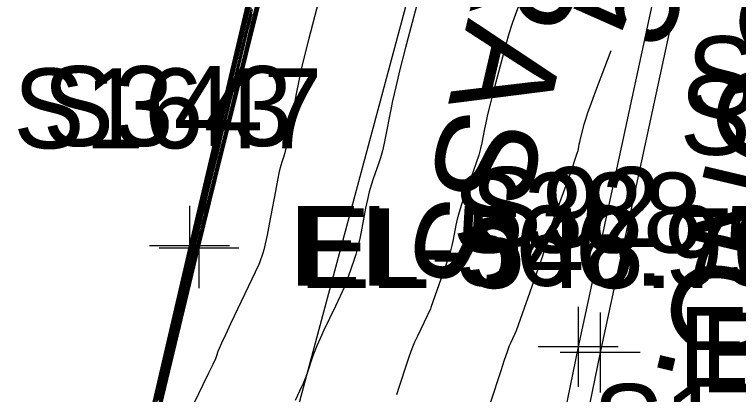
# Model space of a CAD drawing. Extents: x 1724534 to 1727318, y 657156 to 660047.
# Drawn here: x 1725584.68 to 1725620.89, y 659683.28 to 659702.31 of the extents above; entities that cross this region are included whole.
import ezdxf

# ---------------------------------------------------------------- set-up
doc = ezdxf.new("R2010")
doc.units = 0
for name, color, linetype in [('SURVEY - CONTOURS - Index with Text', 7, 'Continuous'), ('SURVEY - CONTOURS - Intermediate with optional Text', 7, 'Continuous'), ('SURVEY - DTM - Breaklines', 7, 'Continuous'), ('SURVEY - DTM - Breaklines - Points - Elevations', 7, 'Continuous'), ('SURVEY - DTM - Breaklines - Points - Locators', 7, 'Continuous'), ('SURVEY - DTM - Breaklines - Points - Numbers', 7, 'Continuous'), ('SURVEY - NON-TRANSPORTATION - Features', 7, 'Continuous'), ('SURVEY - NON-TRANSPORTATION - Features - Points - Elevations', 7, 'Continuous'), ('SURVEY - NON-TRANSPORTATION - Features - Points - Locators', 7, 'Continuous'), ('SURVEY - NON-TRANSPORTATION - Features - Points - Numbers', 7, 'Continuous'), ('SURVEY - TRANSPORTATION - Features', 7, 'Continuous'), ('SURVEY - TRANSPORTATION - Features - Points - Elevations', 7, 'Continuous'), ('SURVEY - TRANSPORTATION - Features - Points - Locators', 7, 'Continuous'), ('SURVEY - TRANSPORTATION - Features - Points - Numbers', 7, 'Continuous'), ('SURVEY - TRANSPORTATION - Features Text', 7, 'Continuous'), ('SURVEY - TRANSPORTATION - Roads - Points - Numbers', 7, 'Continuous'), ('SURVEY - UTILITIES - Fiber Optic Cable (Underground) with Text', 7, 'Continuous'), ('SURVEY - VEGETATION - Features with Text', 7, 'Continuous')]:
    doc.layers.add(name, color=color, linetype=linetype)

msp = doc.modelspace()

# ---------------------------------------------------------------- linework, layer by layer
at = {"layer": 'SURVEY - CONTOURS - Index with Text'}
for points in [[(1725591.606, 659682.65), (1725592.009, 659684.387), (1725592.143, 659684.966), (1725592.245, 659685.403), (1725592.313, 659685.697), (1725592.349, 659685.847), (1725592.399, 659686.058), (1725592.435, 659686.208), (1725592.503, 659686.502), (1725592.605, 659686.939), (1725592.739, 659687.519), (1725593.142, 659689.256), (1725593.274, 659689.826), (1725593.368, 659690.234), (1725593.426, 659690.48), (1725593.445, 659690.564), (1725593.447, 659690.571), (1725593.448, 659690.576), (1725593.45, 659690.586), (1725593.453, 659690.599), (1725593.457, 659690.617), (1725593.47, 659690.671), (1725593.493, 659690.769), (1725593.553, 659691.023), (1725593.65, 659691.433), (1725593.784, 659691.998), (1725594.191, 659693.714), (1725594.328, 659694.287), (1725594.431, 659694.721), (1725594.501, 659695.016), (1725594.539, 659695.171), (1725594.596, 659695.4), (1725594.634, 659695.554), (1725594.704, 659695.846), (1725594.806, 659696.276), (1725594.941, 659696.843), (1725595.343, 659698.539), (1725595.478, 659699.107), (1725595.581, 659699.539), (1725595.652, 659699.836), (1725595.691, 659699.997), (1725595.753, 659700.244), (1725595.792, 659700.404), (1725595.862, 659700.698), (1725595.964, 659701.126), (1725596.098, 659701.688), (1725596.496, 659703.365)], [(1725614.505, 659700.498), (1725613.696, 659698.346), (1725613.501, 659697.82), (1725613.346, 659697.387), (1725613.233, 659697.046), (1725613.16, 659696.799), (1725612.973, 659696.077), (1725612.935, 659695.922), (1725612.906, 659695.797), (1725612.887, 659695.702), (1725612.847, 659695.49), (1725612.806, 659695.342), (1725612.711, 659695.055), (1725612.564, 659694.631), (1725612.364, 659694.069), (1725611.76, 659692.386), (1725611.559, 659691.821), (1725611.411, 659691.389), (1725611.314, 659691.09), (1725611.269, 659690.923), (1725611.218, 659690.655), (1725611.175, 659690.492), (1725611.084, 659690.206), (1725610.945, 659689.795), (1725610.758, 659689.261), (1725609.771, 659686.469), (1725609.498, 659685.893), (1725609.424, 659685.715), (1725609.317, 659685.419), (1725609.175, 659685.005), (1725608.999, 659684.474), (1725608.484, 659682.9)], [(1725595.875, 659698.678), (1725595.138, 659695.716), (1725595.001, 659695.157), (1725593.931, 659690.856), (1725593.677, 659689.786), (1725592.642, 659685.467), (1725592.503, 659684.88), (1725591.476, 659680.593), (1725591.33, 659679.975), (1725590.347, 659675.869), (1725590.312, 659675.719), (1725590.159, 659675.071), (1725588.166, 659666.752), (1725588.013, 659666.093), (1725586.735, 659660.334), (1725586.015, 659657.096)], [(1725591.839, 659683.103), (1725591.939, 659683.535), (1725592.22, 659684.747), (1725592.32, 659685.179), (1725592.411, 659685.567), (1725592.492, 659685.912), (1725592.564, 659686.212), (1725592.742, 659686.954), (1725592.813, 659687.254), (1725592.894, 659687.597), (1725592.985, 659687.983), (1725593.085, 659688.413), (1725593.364, 659689.618), (1725593.456, 659690.014), (1725593.522, 659690.3), (1725593.563, 659690.476), (1725593.578, 659690.541), (1725593.584, 659690.567), (1725593.587, 659690.577), (1725593.59, 659690.589), (1725593.593, 659690.601), (1725593.596, 659690.615), (1725593.604, 659690.652), (1725593.62, 659690.72), (1725593.662, 659690.896), (1725593.729, 659691.18), (1725593.822, 659691.572), (1725593.865, 659691.751)], [(1725593.278, 659688.662), (1725593.085, 659687.85), (1725592.578, 659685.732), (1725592.126, 659683.798), (1725591.424, 659680.865), (1725590.966, 659678.905), (1725590.271, 659675.998), (1725589.807, 659674.012), (1725588.399, 659668.125), (1725588.074, 659666.734), (1725587.908, 659666.01), (1725585.853, 659656.743)]]:
    msp.add_lwpolyline(points, dxfattribs=at)
at = {"layer": 'SURVEY - CONTOURS - Intermediate with optional Text'}
for points in [[(1725599.522, 659713.198), (1725594.751, 659694.03), (1725593.893, 659690.58), (1725591.498, 659680.584), (1725590.349, 659675.79), (1725589.977, 659674.229), (1725588.105, 659666.413), (1725587.991, 659665.913), (1725587.691, 659664.563), (1725586.902, 659661.012), (1725585.92, 659656.591)], [(1725611.985, 659708.312), (1725609.681, 659702.188), (1725609.547, 659701.805), (1725609.402, 659701.343), (1725609.246, 659700.802), (1725609.08, 659700.182), (1725608.623, 659698.424), (1725608.467, 659697.814), (1725608.341, 659697.304), (1725608.246, 659696.894), (1725608.182, 659696.583), (1725608.052, 659695.888), (1725607.989, 659695.603), (1725607.897, 659695.268), (1725607.776, 659694.884), (1725607.626, 659694.451), (1725607.188, 659693.23), (1725607.038, 659692.796), (1725606.916, 659692.407), (1725606.822, 659692.065), (1725606.756, 659691.769), (1725606.618, 659691.042), (1725606.553, 659690.748), (1725606.463, 659690.415), (1725606.348, 659690.04), (1725606.207, 659689.625), (1725605.503, 659687.637), (1725605.48, 659687.574), (1725604.829, 659686.201), (1725604.693, 659685.9), (1725604.557, 659685.565), (1725604.421, 659685.196), (1725604.284, 659684.793), (1725603.919, 659683.675), (1725603.78, 659683.269)], [(1725597.458, 659705.207), (1725596.393, 659700.922), (1725596.256, 659700.353), (1725595.19, 659696.064), (1725595.054, 659695.499), (1725593.987, 659691.206), (1725593.764, 659690.269), (1725593.599, 659689.567), (1725592.639, 659685.562), (1725592.428, 659684.664), (1725591.477, 659680.694), (1725591.258, 659679.761), (1725590.316, 659675.826), (1725590.089, 659674.859), (1725588.197, 659666.958), (1725588.152, 659666.769), (1725587.998, 659666.1), (1725585.808, 659656.238)], [(1725593.678, 659691.782), (1725595.817, 659700.79), (1725596.879, 659705.257)], [(1725597.105, 659704.079), (1725596.504, 659701.666), (1725596.375, 659701.133), (1725596.215, 659700.463), (1725595.909, 659699.226), (1725595.309, 659696.814), (1725595.179, 659696.28), (1725595.019, 659695.61), (1725594.713, 659694.373), (1725594.113, 659691.961), (1725593.983, 659691.428), (1725593.711, 659690.277), (1725593.517, 659689.446), (1725592.568, 659685.477), (1725592.277, 659684.231), (1725591.41, 659680.609), (1725591.112, 659679.333), (1725590.253, 659675.741), (1725589.948, 659674.436), (1725588.334, 659667.694), (1725588.073, 659666.578), (1725587.937, 659665.983), (1725584.959, 659652.565)], [(1725597.088, 659704.163), (1725596.523, 659701.891), (1725596.385, 659701.319), (1725596.194, 659700.519), (1725595.896, 659699.311), (1725595.331, 659697.041), (1725595.192, 659696.469), (1725595.001, 659695.666), (1725594.703, 659694.458), (1725594.139, 659692.191), (1725594, 659691.618), (1725593.674, 659690.24), (1725593.441, 659689.237), (1725593.153, 659688.029), (1725592.611, 659685.765), (1725592.473, 659685.179), (1725592.279, 659684.342), (1725591.992, 659683.139)], [(1725597.121, 659703.995), (1725596.485, 659701.442), (1725596.364, 659700.947), (1725596.236, 659700.408), (1725595.921, 659699.141), (1725595.286, 659696.587), (1725595.165, 659696.092), (1725595.037, 659695.555), (1725594.722, 659694.287), (1725594.086, 659691.731), (1725593.965, 659691.237), (1725593.72, 659690.197), (1725593.521, 659689.348), (1725592.604, 659685.52), (1725592.352, 659684.447), (1725591.444, 659680.652), (1725591.185, 659679.547), (1725590.284, 659675.783), (1725590.018, 659674.647), (1725588.302, 659667.479), (1725588.072, 659666.499), (1725587.949, 659665.958), (1725585.852, 659656.511)], [(1725591.54, 659682.473), (1725591.967, 659684.314), (1725592.108, 659684.924), (1725592.211, 659685.37), (1725592.277, 659685.654), (1725592.306, 659685.774), (1725592.331, 659685.879), (1725592.359, 659685.999), (1725592.425, 659686.283), (1725592.529, 659686.73), (1725592.67, 659687.34), (1725593.097, 659689.183), (1725593.237, 659689.788), (1725593.338, 659690.221), (1725593.398, 659690.481), (1725593.418, 659690.568), (1725593.419, 659690.572), (1725593.42, 659690.576), (1725593.422, 659690.585), (1725593.425, 659690.599), (1725593.43, 659690.618), (1725593.443, 659690.675), (1725593.468, 659690.779), (1725593.532, 659691.049), (1725593.635, 659691.483), (1725593.777, 659692.084), (1725594.209, 659693.904), (1725594.352, 659694.507), (1725594.457, 659694.951), (1725594.525, 659695.236), (1725594.556, 659695.362), (1725594.586, 659695.485), (1725594.616, 659695.61), (1725594.684, 659695.892), (1725594.788, 659696.331), (1725594.93, 659696.927), (1725595.357, 659698.727), (1725595.499, 659699.324), (1725595.604, 659699.766), (1725595.672, 659700.053), (1725595.704, 659700.185), (1725595.74, 659700.329), (1725595.772, 659700.46), (1725595.839, 659700.744), (1725595.944, 659701.181), (1725596.084, 659701.772), (1725596.506, 659703.551)], [(1725591.672, 659682.499), (1725592.378, 659685.535), (1725592.521, 659686.139), (1725592.738, 659687.044), (1725593.016, 659688.234), (1725593.595, 659690.73), (1725594.122, 659692.952), (1725594.23, 659693.407), (1725594.406, 659694.135), (1725594.702, 659695.33), (1725594.984, 659696.505), (1725595.49, 659698.631), (1725595.64, 659699.243), (1725595.873, 659700.181), (1725596.154, 659701.352), (1725596.657, 659703.461)], [(1725605, 659703.565), (1725604.225, 659700.584), (1725603.96, 659699.551), (1725603.747, 659698.686), (1725603.587, 659697.991), (1725603.478, 659697.465), (1725603.257, 659696.286), (1725603.172, 659695.864), (1725603.082, 659695.481), (1725602.988, 659695.137), (1725602.888, 659694.833), (1725602.616, 659694.075), (1725602.516, 659693.771), (1725602.42, 659693.426), (1725602.329, 659693.041), (1725602.243, 659692.616), (1725602.018, 659691.428), (1725601.932, 659691.004), (1725601.843, 659690.623), (1725601.75, 659690.285), (1725601.655, 659689.989), (1725601.248, 659688.839), (1725601.189, 659688.679), (1725600.728, 659687.709), (1725600.159, 659686.51), (1725599.962, 659686.085), (1725599.798, 659685.711), (1725599.668, 659685.387), (1725599.57, 659685.113), (1725599.353, 659684.45), (1725599.253, 659684.172), (1725599.115, 659683.836), (1725598.938, 659683.441), (1725598.724, 659682.988)], [(1725591.673, 659682.827), (1725592.051, 659684.459), (1725592.179, 659685.009), (1725592.278, 659685.436), (1725592.349, 659685.74), (1725592.468, 659686.237), (1725592.51, 659686.417), (1725592.581, 659686.721), (1725592.681, 659687.148), (1725592.808, 659687.698), (1725593.31, 659689.864), (1725593.399, 659690.247), (1725593.453, 659690.479), (1725593.472, 659690.559), (1725593.474, 659690.57), (1725593.478, 659690.586), (1725593.481, 659690.6), (1725593.485, 659690.617), (1725593.497, 659690.667), (1725593.519, 659690.76), (1725593.666, 659691.382), (1725593.792, 659691.913), (1725594.174, 659693.523), (1725594.303, 659694.067), (1725594.404, 659694.491), (1725594.523, 659694.981), (1725594.606, 659695.314), (1725594.651, 659695.498), (1725594.723, 659695.8), (1725594.824, 659696.22), (1725594.952, 659696.758), (1725595.329, 659698.351), (1725595.458, 659698.89), (1725595.558, 659699.312), (1725595.632, 659699.618), (1725595.678, 659699.808), (1725595.812, 659700.348), (1725595.885, 659700.652), (1725595.985, 659701.071), (1725596.112, 659701.604), (1725596.486, 659703.179)], [(1725591.739, 659683.004), (1725592.093, 659684.531), (1725592.214, 659685.051), (1725592.311, 659685.469), (1725592.385, 659685.783), (1725592.435, 659685.993), (1725592.536, 659686.416), (1725592.586, 659686.626), (1725592.66, 659686.94), (1725592.757, 659687.357), (1725592.877, 659687.876), (1725593.231, 659689.4), (1725593.347, 659689.901), (1725593.43, 659690.26), (1725593.48, 659690.478), (1725593.498, 659690.555), (1725593.502, 659690.57), (1725593.504, 659690.577), (1725593.506, 659690.587), (1725593.509, 659690.6), (1725593.513, 659690.616), (1725593.524, 659690.664), (1725593.544, 659690.75), (1725593.597, 659690.972), (1725593.682, 659691.332), (1725593.8, 659691.828), (1725594.157, 659693.333), (1725594.279, 659693.847), (1725594.378, 659694.261), (1725594.454, 659694.576), (1725594.506, 659694.79), (1725594.615, 659695.229), (1725594.668, 659695.442), (1725594.743, 659695.754), (1725594.841, 659696.165), (1725594.962, 659696.674), (1725595.316, 659698.162), (1725595.437, 659698.672), (1725595.536, 659699.085), (1725595.612, 659699.401), (1725595.666, 659699.62), (1725595.779, 659700.074), (1725595.832, 659700.293), (1725595.908, 659700.606), (1725596.006, 659701.015), (1725596.126, 659701.52), (1725596.476, 659702.993)], [(1725599.883, 659702.961), (1725599.382, 659701.036), (1725599.203, 659700.327), (1725599.042, 659699.642), (1725598.899, 659698.981), (1725598.773, 659698.346), (1725598.463, 659696.684), (1725598.356, 659696.124), (1725598.268, 659695.693), (1725598.199, 659695.39), (1725598.15, 659695.215), (1725598.044, 659694.92), (1725597.994, 659694.745), (1725597.925, 659694.444), (1725597.837, 659694.017), (1725597.73, 659693.462), (1725597.417, 659691.815), (1725597.31, 659691.26), (1725597.222, 659690.832), (1725597.153, 659690.53), (1725597.103, 659690.353), (1725596.932, 659689.872), (1725596.897, 659689.784), (1725595.49, 659686.818), (1725595.231, 659686.27), (1725595.039, 659685.857), (1725594.914, 659685.578), (1725594.855, 659685.433), (1725594.787, 659685.225), (1725594.726, 659685.076), (1725594.592, 659684.783), (1725594.385, 659684.346), (1725594.106, 659683.766), (1725592.989, 659681.452)], [(1725591.806, 659683.181), (1725592.135, 659684.603), (1725592.25, 659685.094), (1725592.345, 659685.502), (1725592.421, 659685.826), (1725592.478, 659686.066), (1725592.605, 659686.595), (1725592.662, 659686.835), (1725592.738, 659687.159), (1725592.833, 659687.565), (1725592.947, 659688.055), (1725593.275, 659689.473), (1725593.383, 659689.939), (1725593.461, 659690.274), (1725593.508, 659690.477), (1725593.525, 659690.55), (1725593.529, 659690.569), (1725593.531, 659690.577), (1725593.534, 659690.587), (1725593.537, 659690.6), (1725593.54, 659690.616), (1725593.551, 659690.66), (1725593.57, 659690.74), (1725593.619, 659690.947), (1725593.698, 659691.281), (1725593.807, 659691.743), (1725594.139, 659693.142), (1725594.254, 659693.627), (1725594.351, 659694.031), (1725594.43, 659694.356), (1725594.49, 659694.6), (1725594.625, 659695.143), (1725594.685, 659695.386), (1725594.763, 659695.708), (1725594.859, 659696.109), (1725594.973, 659696.589), (1725595.302, 659697.974), (1725595.416, 659698.455), (1725595.513, 659698.858), (1725595.592, 659699.183), (1725595.653, 659699.432), (1725595.792, 659699.99), (1725595.853, 659700.237), (1725595.931, 659700.56), (1725596.027, 659700.96), (1725596.14, 659701.436), (1725596.466, 659702.807)], [(1725591.823, 659682.932), (1725591.912, 659683.309), (1725592.006, 659683.712), (1725592.262, 659684.819), (1725592.356, 659685.222), (1725592.445, 659685.6), (1725592.528, 659685.955), (1725592.607, 659686.285), (1725592.811, 659687.133), (1725592.889, 659687.463), (1725592.973, 659687.816), (1725593.061, 659688.192), (1725593.154, 659688.592), (1725593.408, 659689.69), (1725593.492, 659690.052), (1725593.553, 659690.313), (1725593.59, 659690.475), (1725593.605, 659690.536), (1725593.612, 659690.566), (1725593.615, 659690.578), (1725593.618, 659690.589), (1725593.62, 659690.602), (1725593.623, 659690.614), (1725593.631, 659690.648), (1725593.646, 659690.71), (1725593.684, 659690.871), (1725593.745, 659691.13), (1725593.83, 659691.487), (1725594.087, 659692.571), (1725594.181, 659692.967), (1725594.272, 659693.341), (1725594.358, 659693.695), (1725594.44, 659694.028), (1725594.654, 659694.886), (1725594.736, 659695.218), (1725594.822, 659695.571), (1725594.912, 659695.943), (1725595.006, 659696.336), (1725595.261, 659697.41), (1725595.355, 659697.803), (1725595.445, 659698.177), (1725595.531, 659698.531), (1725595.614, 659698.866), (1725595.831, 659699.735), (1725595.914, 659700.07), (1725596, 659700.423), (1725596.09, 659700.795), (1725596.183, 659701.185), (1725596.435, 659702.249), (1725596.529, 659702.639)], [(1725591.886, 659682.993), (1725591.975, 659683.365), (1725592.059, 659683.722), (1725592.139, 659684.066), (1725592.347, 659684.963), (1725592.427, 659685.307), (1725592.511, 659685.666), (1725592.948, 659687.491), (1725593.041, 659687.881), (1725593.129, 659688.254), (1725593.213, 659688.61), (1725593.292, 659688.95), (1725593.497, 659689.835), (1725593.565, 659690.127), (1725593.614, 659690.34), (1725593.645, 659690.473), (1725593.658, 659690.527), (1725593.667, 659690.564), (1725593.67, 659690.578), (1725593.673, 659690.591), (1725593.676, 659690.602), (1725593.697, 659690.691), (1725593.727, 659690.82), (1725593.777, 659691.028), (1725593.845, 659691.316), (1725594.052, 659692.19), (1725594.133, 659692.526), (1725594.219, 659692.881), (1725594.31, 659693.255), (1725594.407, 659693.646), (1725594.674, 659694.715), (1725594.771, 659695.106), (1725594.862, 659695.479), (1725594.948, 659695.832), (1725595.028, 659696.167), (1725595.314, 659697.368), (1725595.399, 659697.722), (1725595.491, 659698.096), (1725595.857, 659699.565), (1725595.954, 659699.958), (1725596.046, 659700.331), (1725596.131, 659700.684), (1725596.211, 659701.017), (1725596.415, 659701.877), (1725596.495, 659702.21), (1725596.581, 659702.564)], [(1725591.899, 659683.148), (1725591.985, 659683.516), (1725592.072, 659683.889), (1725592.304, 659684.891), (1725592.391, 659685.264), (1725592.478, 659685.633), (1725592.564, 659685.998), (1725592.65, 659686.358), (1725592.879, 659687.312), (1725592.965, 659687.672), (1725593.051, 659688.035), (1725593.137, 659688.401), (1725593.223, 659688.771), (1725593.453, 659689.762), (1725593.529, 659690.089), (1725593.584, 659690.326), (1725593.618, 659690.474), (1725593.631, 659690.531), (1725593.64, 659690.565), (1725593.643, 659690.578), (1725593.645, 659690.59), (1725593.648, 659690.602), (1725593.651, 659690.614), (1725593.658, 659690.644), (1725593.671, 659690.7), (1725593.706, 659690.845), (1725593.761, 659691.079), (1725593.838, 659691.402), (1725594.07, 659692.38), (1725594.157, 659692.747), (1725594.245, 659693.111), (1725594.334, 659693.475), (1725594.424, 659693.837), (1725594.664, 659694.801), (1725594.754, 659695.162), (1725594.842, 659695.525), (1725594.93, 659695.888), (1725595.017, 659696.251), (1725595.247, 659697.221), (1725595.334, 659697.585), (1725595.422, 659697.949), (1725595.511, 659698.314), (1725595.602, 659698.678), (1725595.844, 659699.65), (1725595.934, 659700.014), (1725596.023, 659700.377), (1725596.11, 659700.739), (1725596.197, 659701.101), (1725596.425, 659702.063), (1725596.512, 659702.425)], [(1725591.959, 659683.2), (1725592.05, 659683.581), (1725592.132, 659683.929), (1725592.205, 659684.243), (1725592.389, 659685.035), (1725592.462, 659685.349), (1725592.544, 659685.699), (1725593.016, 659687.67), (1725593.117, 659688.09), (1725593.208, 659688.472), (1725593.289, 659688.819), (1725593.361, 659689.129), (1725593.542, 659689.907), (1725593.602, 659690.165), (1725593.645, 659690.353), (1725593.673, 659690.472), (1725593.685, 659690.522), (1725593.695, 659690.563), (1725593.698, 659690.578), (1725593.701, 659690.591), (1725593.704, 659690.603), (1725593.722, 659690.681), (1725593.749, 659690.794), (1725593.853, 659691.231), (1725594.035, 659691.999), (1725594.108, 659692.306), (1725594.192, 659692.651), (1725594.286, 659693.035), (1725594.391, 659693.456), (1725594.683, 659694.629), (1725594.788, 659695.05), (1725594.882, 659695.433), (1725594.966, 659695.777), (1725595.039, 659696.082), (1725595.293, 659697.151), (1725595.377, 659697.495), (1725595.471, 659697.879), (1725595.576, 659698.301), (1725595.87, 659699.48), (1725595.974, 659699.903), (1725596.069, 659700.286), (1725596.152, 659700.629), (1725596.225, 659700.933), (1725596.405, 659701.691), (1725596.478, 659701.995), (1725596.562, 659702.339)]]:
    msp.add_lwpolyline(points, dxfattribs=at)
at = {"layer": 'SURVEY - DTM - Breaklines'}
for points in [[(1725548.52, 659521.481), (1725556.845, 659545.065), (1725562.116, 659569.482), (1725564.828, 659594.513), (1725575.937, 659617.765), (1725582.317, 659641.569), (1725587.744, 659666.22), (1725593.428, 659690.724), (1725599.084, 659714.698), (1725604.574, 659739.361), (1725605.919, 659744.429), (1725611.764, 659762.844), (1725613.112, 659786.858), (1725615.798, 659788.854), (1725620.104, 659809.038)], [(1725639.982, 659805.546), (1725635.79, 659784.47), (1725629.921, 659758.494), (1725625.443, 659739.387), (1725624.054, 659734.362), (1725618.103, 659709.974), (1725612.874, 659685.67), (1725607.844, 659661.097), (1725602.477, 659636.589), (1725597.046, 659612.281)]]:
    msp.add_lwpolyline(points, dxfattribs=at)
at = {"layer": 'SURVEY - DTM - Breaklines - Points - Locators'}
for p, q in [((1725593.428, 659692.724), (1725593.428, 659688.724)), ((1725595.428, 659690.724), (1725591.428, 659690.724)), ((1725612.874, 659687.67), (1725612.874, 659683.67)), ((1725614.874, 659685.67), (1725610.874, 659685.67))]:
    msp.add_line(p, q, dxfattribs=at)
at = {"layer": 'SURVEY - NON-TRANSPORTATION - Features'}
msp.add_lwpolyline([(1725569.664, 659593.303), (1725577.056, 659617.422), (1725582.603, 659641.503), (1725588.069, 659666.147), (1725593.908, 659690.609), (1725599.872, 659714.501), (1725606.018, 659738.998), (1725607.394, 659744.026), (1725612.585, 659762.615), (1725617.711, 659786.227), (1725616.679, 659788.487), (1725620.281, 659809.007)], dxfattribs=at)
at = {"layer": 'SURVEY - NON-TRANSPORTATION - Features - Points - Locators'}
for p, q in [((1725593.908, 659692.609), (1725593.908, 659688.609)), ((1725595.908, 659690.609), (1725591.908, 659690.609))]:
    msp.add_line(p, q, dxfattribs=at)
at = {"layer": 'SURVEY - TRANSPORTATION - Features'}
msp.add_lwpolyline([(1725641.101, 659805.349), (1725636.902, 659784.236), (1725631.028, 659758.231), (1725626.544, 659739.104), (1725625.155, 659734.079), (1725619.206, 659709.701), (1725613.974, 659685.384), (1725608.945, 659660.816), (1725603.581, 659636.317), (1725598.147, 659611.998)], dxfattribs=at)
at = {"layer": 'SURVEY - TRANSPORTATION - Features - Points - Locators'}
for p, q in [((1725613.974, 659687.384), (1725613.974, 659683.384)), ((1725615.974, 659685.384), (1725611.974, 659685.384))]:
    msp.add_line(p, q, dxfattribs=at)
at = {"layer": 'SURVEY - UTILITIES - Fiber Optic Cable (Underground) with Text'}
msp.add_lwpolyline([(1725620.739, 659775.717), (1725611.515, 659729.876), (1725595.678, 659670.817), (1725588.852, 659637.987), (1725579.945, 659608.985), (1725572.052, 659574.699), (1725561.954, 659530.586), (1725538.949, 659448.715), (1725526.808, 659392.271), (1725505.744, 659313.434), (1725493.556, 659248.407)], dxfattribs=at)

# ---------------------------------------------------------------- texts
at = {"layer": 'SURVEY - CONTOURS - Index with Text'}
msp.add_text('545', height=5, rotation=69.3885, dxfattribs=at).set_placement((1725617.117, 659700.339))
at = {"layer": 'SURVEY - DTM - Breaklines - Points - Elevations'}
for s, p in [('EL-566.95', (1725598.428, 659688.724)), ('EL-544.28', (1725617.874, 659683.67))]:
    msp.add_text(s, height=4, dxfattribs=at).set_placement(p)
at = {"layer": 'SURVEY - DTM - Breaklines - Points - Numbers'}
for s, p in [('S343', (1725586.092, 659695.724)), ('S92', (1725607.49, 659690.67))]:
    msp.add_text(s, height=4, dxfattribs=at).set_placement(p)
at = {"layer": 'SURVEY - NON-TRANSPORTATION - Features - Points - Elevations'}
msp.add_text('EL-548.70', height=4, dxfattribs=at).set_placement((1725598.908, 659688.609))
at = {"layer": 'SURVEY - NON-TRANSPORTATION - Features - Points - Numbers'}
msp.add_text('S1647', height=4, dxfattribs=at).set_placement((1725584.62, 659695.609))
at = {"layer": 'SURVEY - TRANSPORTATION - Features - Points - Elevations'}
msp.add_text('EL-544.12', height=4, dxfattribs=at).set_placement((1725618.974, 659683.384))
at = {"layer": 'SURVEY - TRANSPORTATION - Features - Points - Numbers'}
msp.add_text('S388', height=4, dxfattribs=at).set_placement((1725606.591, 659690.384))
at = {"layer": 'SURVEY - TRANSPORTATION - Features Text'}
msp.add_text('CONC.', height=5, rotation=256.6327, dxfattribs=at).set_placement((1725621.668, 659705.002))
at = {"layer": 'SURVEY - TRANSPORTATION - Roads - Points - Numbers'}
for s, p in [('S1412', (1725618.284, 659697.221)), ('S1411', (1725617.944, 659695.284)), ('S1410', (1725613.582, 659679.805))]:
    msp.add_text(s, height=4, dxfattribs=at).set_placement(p)
at = {"layer": 'SURVEY - VEGETATION - Features with Text'}
msp.add_text('GRASS', height=5, rotation=256.97, dxfattribs=at).set_placement((1725609.63, 659711.94))

doc.saveas('drawing.dxf')
